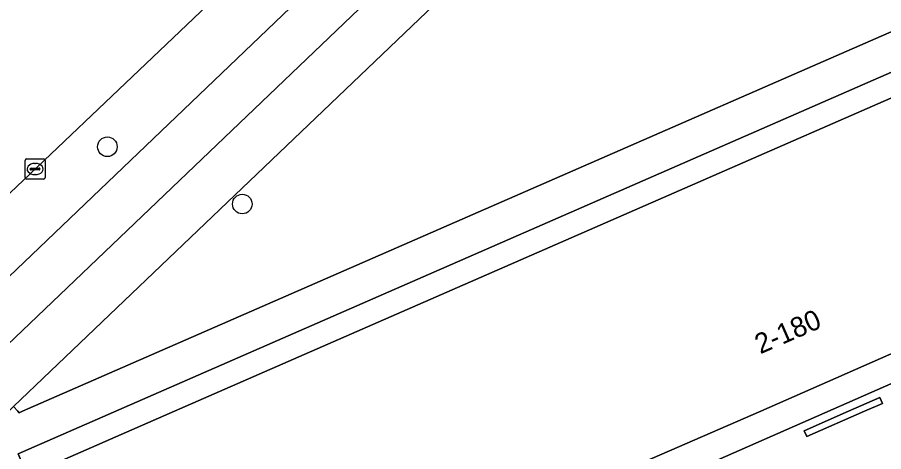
# Model space of a CAD drawing. Extents: x 159960 to 160866, y 382700 to 383354.
# Drawn here: x 160221.54 to 160264.81, y 382997.98 to 383019.66 of the extents above; entities that cross this region are included whole.
import ezdxf

# ---------------------------------------------------------------- set-up
doc = ezdxf.new("R2010")
doc.units = 0
for name, color, linetype in [('IMGEO_Berm_groen', 7, 'Continuous'), ('IMGEO_Boom', 7, 'Continuous'), ('IMGEO_Erf', 7, 'Continuous'), ('IMGEO_Fietspad_open', 7, 'Continuous'), ('IMGEO_Groenvoorziening', 7, 'Continuous'), ('IMGEO_Kolk', 7, 'Continuous'), ('IMGEO_Pand', 7, 'Continuous'), ('IMGEO_Pand_nummerreeks', 7, 'Continuous'), ('IMGEO_Rijbaan_lokaal_gesloten', 7, 'Continuous'), ('IMGEO_Voetpad_open', 7, 'Continuous')]:
    doc.layers.add(name, color=color, linetype=linetype)

msp = doc.modelspace()

# ---------------------------------------------------------------- linework, layer by layer
at = {"layer": 'IMGEO_Berm_groen'}
msp.add_lwpolyline([(160241.075, 383030.001), (160234.099, 383023.201), (160228.63, 383017.988), (160213.006, 383003.15), (160205.896, 382996.376), (160207.97, 382994.198), (160210.466, 382996.565), (160244.662, 383029.223)], dxfattribs=at)
at = {"layer": 'IMGEO_Boom'}
for centre in [(160226.033, 383013.201), (160232.773, 383010.343)]:
    msp.add_circle(centre, 0.489, dxfattribs=at)
at = {"layer": 'IMGEO_Erf'}
for points in [[(160297.308, 383016.984), (160258.674, 383000), (160226.74, 382986.142), (160227.406, 382984.773), (160297.863, 383015.722)], [(160263.85, 383000), (160264.752, 383000.395), (160264.625, 383000.684), (160263.062, 383000), (160260.844, 382999.029), (160260.971, 382998.74)]]:
    msp.add_lwpolyline(points, close=True, dxfattribs=at)
at = {"layer": 'IMGEO_Fietspad_open'}
for points in [[(160354.266, 383138.215), (160344.403, 383127.954), (160330.202, 383113.614), (160265.151, 383048.791), (160244.662, 383029.223), (160210.466, 382996.565), (160207.97, 382994.198), (160203.849, 382990.29), (160202.18, 382988.665), (160201.881, 382988.378)], [(160203.096, 382986.199), (160266.621, 383046.833), (160320.923, 383101.092)]]:
    msp.add_lwpolyline(points, dxfattribs=at)
at = {"layer": 'IMGEO_Groenvoorziening'}
msp.add_lwpolyline([(160315.353, 383049.161), (160300.321, 383064.084), (160296.246, 383068.169), (160293.902, 383070.519), (160267.761, 383044.535), (160221.343, 383000.23), (160221.557, 383000), (160221.626, 382999.926), (160221.796, 383000), (160291.641, 383030.493)], close=True, dxfattribs=at)
at = {"layer": 'IMGEO_Kolk'}
for p, q in [((160221.922, 383011.665), (160221.922, 383012.517)), ((160221.997, 383012.591), (160222.849, 383012.591)), ((160222.41, 383012.371), (160222.435, 383012.371)), ((160222.923, 383012.517), (160222.923, 383011.665)), ((160222.181, 383012.085), (160222.181, 383012.097)), ((160222.619, 383012.048), (160222.221, 383012.048)), ((160222.224, 383012.134), (160222.622, 383012.134)), ((160222.433, 383011.811), (160222.408, 383011.811)), ((160222.665, 383012.097), (160222.665, 383012.085)), ((160222.849, 383011.591), (160221.997, 383011.591))]:
    msp.add_line(p, q, dxfattribs=at)
for points in [[(160221.922, 383011.665), (160221.922, 383012.517)], [(160221.997, 383012.591), (160222.849, 383012.591)], [(160222.923, 383012.517), (160222.923, 383011.665)], [(160222.849, 383011.591), (160221.997, 383011.591)]]:
    msp.add_lwpolyline(points, dxfattribs=at)
for centre, radius, start, end in [((160221.999, 383012.515), 0.0765, 91.552, 178.448), ((160221.999, 383012.515), 0.0765, 91.552, 178.448), ((160222.847, 383012.515), 0.0765, 1.552, 88.448), ((160222.847, 383012.515), 0.0765, 1.552, 88.448), ((160222.221, 383012.094), 0.0403, 85.8775, 175.7526), ((160222.218, 383012.084), 0.0366, 178.938, 274.7102), ((160222.622, 383012.091), 0.043, 264.8664, 352.4533), ((160222.626, 383012.096), 0.0386, 1.7309, 96.639), ((160221.999, 383011.667), 0.0765, 181.552, 268.448), ((160221.999, 383011.667), 0.0765, 181.552, 268.448), ((160222.847, 383011.667), 0.0765, 271.552, 358.448), ((160222.847, 383011.667), 0.0765, 271.552, 358.448)]:
    msp.add_arc(centre, radius, start, end, dxfattribs=at)
for centre, major_axis, ratio, start_param, end_param in [((160222.409, 383012.091), (-0.387, 0.002), 0.722429, 4.712389, 7.853982), ((160222.434, 383012.091), (-0.39, 0.002), 0.717154, 1.570796, 4.712389)]:
    msp.add_ellipse(centre, major_axis=major_axis, ratio=ratio, start_param=start_param, end_param=end_param, dxfattribs=at)
at = {"layer": 'IMGEO_Pand'}
msp.add_lwpolyline([(160226.74, 382986.142), (160258.674, 383000), (160297.308, 383016.984), (160292.649, 383027.642), (160229.378, 383000), (160222.051, 382996.799)], close=True, dxfattribs=at)
at = {"layer": 'IMGEO_Rijbaan_lokaal_gesloten'}
msp.add_lwpolyline([(160241.075, 383030.001), (160262.093, 383050.07), (160262.97, 383050.94), (160257.319, 383056.597), (160253.577, 383052.895), (160239.281, 383039.309), (160237.264, 383037.374), (160230.481, 383031.072), (160229.941, 383030.558), (160214.674, 383015.938), (160214.488, 383015.79), (160200.211, 383002.11), (160205.776, 382996.262), (160205.896, 382996.376), (160213.006, 383003.15), (160228.63, 383017.988), (160234.099, 383023.201)], close=True, dxfattribs=at)
at = {"layer": 'IMGEO_Voetpad_open'}
for points in [[(160359.534, 383140.192), (160355.084, 383135.582), (160349.301, 383129.494), (160346.069, 383126.243), (160333.013, 383113.184), (160320.923, 383101.092), (160266.621, 383046.833), (160203.096, 382986.199), (160209.403, 382984.888)], [(160209.145, 382988.27), (160214.319, 382993.195), (160221.343, 383000.23), (160267.761, 383044.535), (160293.902, 383070.519)], [(160291.641, 383030.493), (160292.175, 383028.72), (160292.649, 383027.642), (160297.308, 383016.984), (160297.863, 383015.722), (160227.406, 382984.773), (160218.256, 382980.741)]]:
    msp.add_lwpolyline(points, dxfattribs=at)
for points in [[(160292.175, 383028.72), (160291.641, 383030.493), (160221.796, 383000), (160221.626, 382999.926), (160221.557, 383000), (160221.343, 383000.23), (160214.319, 382993.195), (160222.051, 382996.799), (160221.58, 382997.876)], [(160292.175, 383028.72), (160221.58, 382997.876), (160222.051, 382996.799), (160229.378, 383000), (160292.649, 383027.642)], [(160264.752, 383000.395), (160263.85, 383000), (160260.971, 382998.74), (160260.844, 382999.029), (160263.062, 383000), (160264.625, 383000.684)]]:
    msp.add_lwpolyline(points, close=True, dxfattribs=at)

# ---------------------------------------------------------------- texts
at = {"layer": 'IMGEO_Pand_nummerreeks'}
msp.add_text('2-180', height=1, rotation=23.6079, dxfattribs=at).set_placement((160258.649, 383002.838))

doc.saveas('drawing.dxf')
